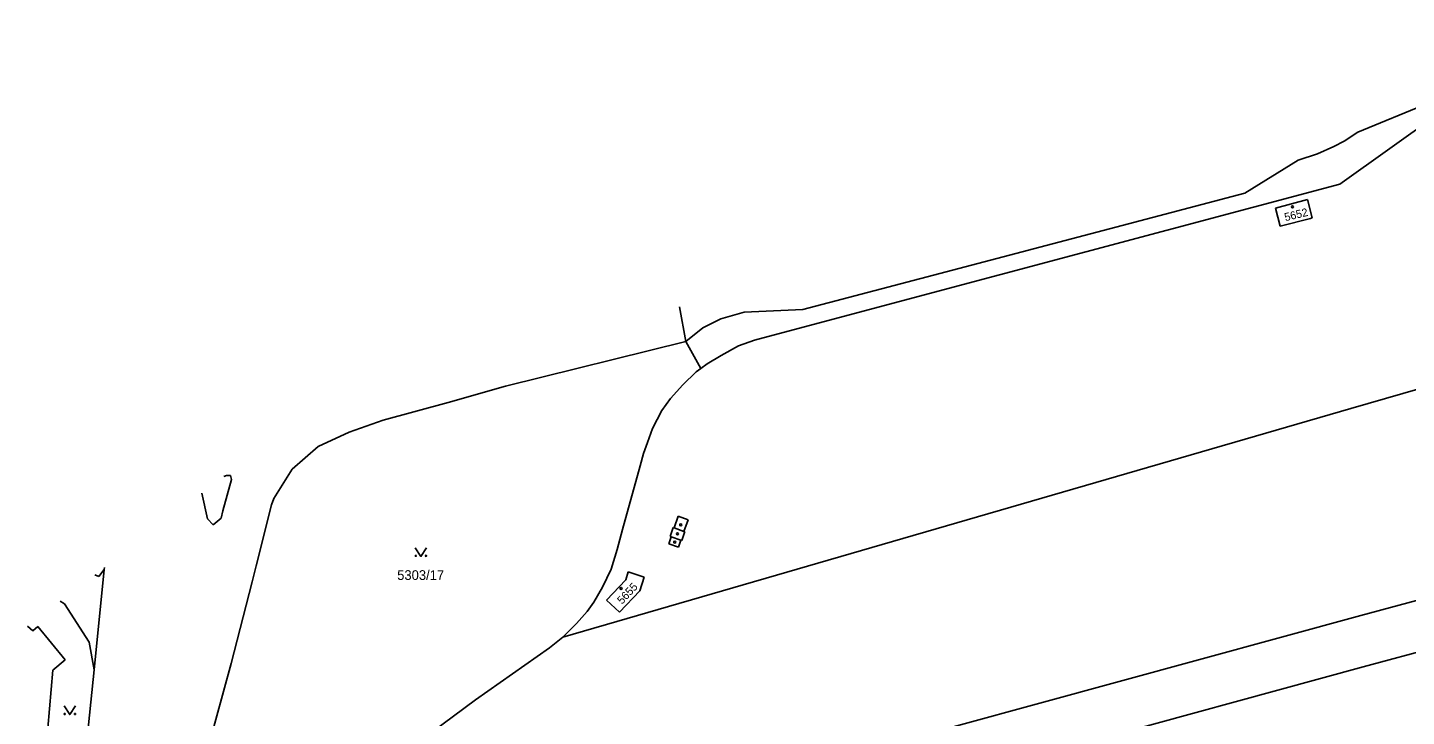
# Model space of a CAD drawing. Extents: x -825057 to -819383, y -1071633 to -1067888.
# Drawn here: x -821889.5 to -821648.2, y -1070225.1 to -1070104.6 of the extents above; entities that cross this region are included whole.
import ezdxf

# ---------------------------------------------------------------- set-up
doc = ezdxf.new("R2010")
doc.units = 0
for name, color, linetype in [('Vrstva 1', 7, 'Continuous'), ('Vrstva 18', 7, 'Continuous'), ('Vrstva 19', 7, 'Continuous'), ('Vrstva 25', 7, 'Continuous'), ('Vrstva 4', 7, 'Continuous')]:
    doc.layers.add(name, color=color, linetype=linetype)

msp = doc.modelspace()

# ---------------------------------------------------------------- linework, layer by layer
at = {"layer": 'Vrstva 1'}
for p, q in [((-821621.57, -1070104.56), (-821659.89, -1070131.96)), ((-821659.89, -1070131.96), (-821734.56, -1070151.86)), ((-821671.16, -1070136.18), (-821665.56, -1070134.66)), ((-821665.56, -1070134.66), (-821664.7, -1070137.89)), ((-821670.31, -1070139.32), (-821671.16, -1070136.18)), ((-821665.03, -1070137.97), (-821670.31, -1070139.32)), ((-821664.7, -1070137.89), (-821665.03, -1070137.97)), ((-821657.98, -1070171.24), (-821560.5, -1070142.95)), ((-821734.56, -1070151.86), (-821762.3, -1070159.26)), ((-821774.34, -1070159.52), (-821775.44, -1070153.45)), ((-821774.34, -1070159.52), (-821805.86, -1070167.31)), ((-821771.7, -1070164.23), (-821774.34, -1070159.52)), ((-821762.3, -1070159.26), (-821765.08, -1070160.28)), ((-821768.14, -1070161.94), (-821770.58, -1070163.41)), ((-821765.08, -1070160.28), (-821768.14, -1070161.94)), ((-821771.7, -1070164.23), (-821772.52, -1070164.83)), ((-821770.58, -1070163.41), (-821771.7, -1070164.23)), ((-821772.52, -1070164.83), (-821774.84, -1070167.08)), ((-821805.86, -1070167.31), (-821815.92, -1070170.17)), ((-821774.84, -1070167.08), (-821776.99, -1070169.48)), ((-821656.22, -1070207.49), (-821511.13, -1070167.91)), ((-821815.92, -1070170.17), (-821827.29, -1070173.28)), ((-821795.84, -1070211.25), (-821657.98, -1070171.24)), ((-821778.53, -1070171.61), (-821780.16, -1070174.72)), ((-821776.99, -1070169.48), (-821778.53, -1070171.61)), ((-821827.29, -1070173.28), (-821833.22, -1070175.38)), ((-821833.22, -1070175.38), (-821838.65, -1070177.87)), ((-821780.16, -1070174.72), (-821781.03, -1070177.19)), ((-821838.65, -1070177.87), (-821843.21, -1070181.88)), ((-821781.03, -1070177.19), (-821781.72, -1070179.14)), ((-821782.32, -1070181.25), (-821785.43, -1070192.45)), ((-821781.72, -1070179.14), (-821782.32, -1070181.25)), ((-821843.21, -1070181.88), (-821846.44, -1070187.02)), ((-821846.8, -1070188.13), (-821849.49, -1070198.77)), ((-821846.44, -1070187.02), (-821846.8, -1070188.13)), ((-821785.43, -1070192.45), (-821786.35, -1070195.94)), ((-821786.35, -1070195.94), (-821787.39, -1070199.35)), ((-821876.08, -1070199.43), (-821877.85, -1070216.96)), ((-821876.05, -1070199.08), (-821876.08, -1070199.43)), ((-821849.49, -1070198.77), (-821850.2, -1070201.61)), ((-821787.39, -1070199.35), (-821788.91, -1070202.52)), ((-821784.85, -1070201.23), (-821784.41, -1070199.86)), ((-821784.41, -1070199.86), (-821781.63, -1070200.75)), ((-821781.63, -1070200.75), (-821782.4, -1070203.13)), ((-821850.2, -1070201.61), (-821853.88, -1070215.88)), ((-821788.91, -1070202.52), (-821790.4, -1070205.13)), ((-821788.19, -1070204.82), (-821784.85, -1070201.23)), ((-821782.4, -1070203.13), (-821785.94, -1070206.91)), ((-821883.78, -1070204.99), (-821883.02, -1070205.42)), ((-821883.02, -1070205.42), (-821878.72, -1070212.12)), ((-821790.4, -1070205.13), (-821791.59, -1070206.8)), ((-821785.94, -1070206.91), (-821788.19, -1070204.82)), ((-821791.59, -1070206.8), (-821793.44, -1070208.9)), ((-821770.97, -1070238.79), (-821656.22, -1070207.49)), ((-821889.51, -1070209.36), (-821888.6, -1070210.18)), ((-821888.6, -1070210.18), (-821887.7, -1070209.43)), ((-821887.7, -1070209.43), (-821882.95, -1070215.26)), ((-821793.44, -1070208.9), (-821795.84, -1070211.25)), ((-821878.72, -1070212.12), (-821877.85, -1070216.96)), ((-821795.84, -1070211.25), (-821798.18, -1070213.11)), ((-821798.18, -1070213.11), (-821811.14, -1070222.26)), ((-821885.09, -1070217.04), (-821887.37, -1070243.06)), ((-821882.95, -1070215.26), (-821885.09, -1070217.04)), ((-821877.85, -1070216.96), (-821881.44, -1070252.03)), ((-821853.88, -1070215.88), (-821860.28, -1070239.36)), ((-821811.14, -1070222.26), (-821820.66, -1070229.3))]:
    msp.add_line(p, q, dxfattribs=at)
at = {"layer": 'Vrstva 25'}
for points in [[(-821819.68, -1070195.63), (-821820.68, -1070197.13), (-821821.68, -1070195.63)], [(-821881.12, -1070223.31), (-821882.12, -1070224.81), (-821883.12, -1070223.31)]]:
    msp.add_lwpolyline(points, dxfattribs=at)
for centre, radius in [((-821668.18, -1070135.95), 0.175), ((-821775.8, -1070193.16), 0.175), ((-821775.22, -1070191.6), 0.175), ((-821776.27, -1070194.62), 0.175), ((-821821.58, -1070197.03), 0.1), ((-821819.78, -1070197.03), 0.1), ((-821785.66, -1070202.74), 0.175), ((-821883.02, -1070224.71), 0.1), ((-821881.22, -1070224.71), 0.1)]:
    msp.add_circle(centre, radius, dxfattribs=at)
at = {"layer": 'Vrstva 4'}
for p, q in [((-821656.73, -1070122.89), (-821644.52, -1070117.83)), ((-821659.14, -1070124.45), (-821656.73, -1070122.89)), ((-821663.79, -1070126.64), (-821660.9, -1070125.36)), ((-821660.9, -1070125.36), (-821659.14, -1070124.45)), ((-821676.51, -1070133.56), (-821667.19, -1070127.8)), ((-821667.19, -1070127.8), (-821663.79, -1070126.64)), ((-821700.19, -1070139.78), (-821676.51, -1070133.56)), ((-821728.77, -1070147.29), (-821700.19, -1070139.78)), ((-821753.87, -1070153.92), (-821728.77, -1070147.29)), ((-821768.17, -1070155.54), (-821764.14, -1070154.4)), ((-821764.14, -1070154.4), (-821753.87, -1070153.92)), ((-821774.34, -1070159.52), (-821771.37, -1070157.15)), ((-821771.37, -1070157.15), (-821768.17, -1070155.54)), ((-821655.78, -1070216.48), (-821508.81, -1070176.39)), ((-821853.81, -1070183.66), (-821855.34, -1070189.18)), ((-821855.16, -1070183.12), (-821854.72, -1070182.96)), ((-821854.72, -1070182.96), (-821854, -1070182.95)), ((-821854, -1070182.95), (-821853.81, -1070183.66)), ((-821858, -1070190.53), (-821858.99, -1070186.05)), ((-821857.05, -1070191.62), (-821858, -1070190.53)), ((-821855.66, -1070190.41), (-821857.05, -1070191.62)), ((-821855.34, -1070189.18), (-821855.66, -1070190.41)), ((-821776.36, -1070192.16), (-821775.64, -1070190.1)), ((-821775.64, -1070190.1), (-821773.92, -1070190.74)), ((-821773.92, -1070190.74), (-821774.67, -1070192.75)), ((-821777.07, -1070193.63), (-821776.53, -1070192.1)), ((-821776.53, -1070192.1), (-821776.36, -1070192.16)), ((-821776.36, -1070192.16), (-821774.67, -1070192.75)), ((-821774.52, -1070192.8), (-821775.03, -1070194.32)), ((-821774.67, -1070192.75), (-821774.52, -1070192.8)), ((-821777.31, -1070194.93), (-821776.89, -1070193.69)), ((-821775.6, -1070195.51), (-821777.31, -1070194.93)), ((-821776.89, -1070193.69), (-821777.07, -1070193.63)), ((-821775.18, -1070194.27), (-821776.89, -1070193.69)), ((-821775.18, -1070194.27), (-821775.6, -1070195.51)), ((-821775.03, -1070194.32), (-821775.18, -1070194.27)), ((-821877.04, -1070200.65), (-821877.74, -1070200.37)), ((-821876.08, -1070199.43), (-821877.04, -1070200.65)), ((-821768.65, -1070247.26), (-821655.78, -1070216.48))]:
    msp.add_line(p, q, dxfattribs=at)

# ---------------------------------------------------------------- texts
at = {"layer": 'Vrstva 18'}
msp.add_text('5303/17', height=1.7, dxfattribs=at).set_placement((-821824.832, -1070201.25))
at = {"layer": 'Vrstva 19'}
for s, rotation, p in [('5652', 13.5, (-821669.403, -1070138.468)), ('5655', 46.8, (-821785.478, -1070205.599))]:
    msp.add_text(s, height=1.4, rotation=rotation, dxfattribs=at).set_placement(p)

doc.saveas('drawing.dxf')
